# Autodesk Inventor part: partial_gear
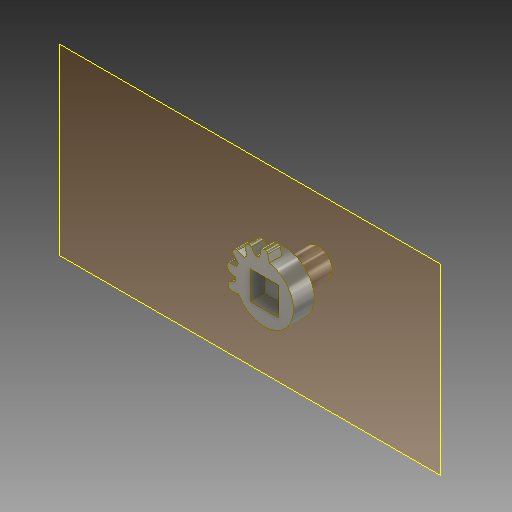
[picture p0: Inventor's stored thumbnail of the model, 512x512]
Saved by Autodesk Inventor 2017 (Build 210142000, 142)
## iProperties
Created: 2017-05
Part Number: partial_gear
Material: Silver
Document SubType Name: Modeling
Designer: 1717440
Density: 10.49 g/cm^3
Appearance: Silver
Author: 1717440
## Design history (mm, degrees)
workplane "Work Plane1"
sketch "Sketch1"
  geometry: L1 (-87.484, -3.82)-(-87.484, 3.711) reference; L2 (-87.484, -3.82)-(-66.896, -5.26) reference; L3 (-42.959, -22.554)-(20.041, -22.554) reference; L4 (20.041, 22.446)-(-42.959, 22.446) reference; L5 (-66.896, 5.151)-(-87.484, 3.711) reference; L6 (-28.459, -15.054)-(-29.709, -12.889) reference; L7 (-29.709, -12.889)-(-33.709, -12.889) reference; L8 (-33.709, -12.889)-(-34.959, -15.054) reference; L9 (-34.959, -15.054)-(-42.959, -15.054) reference; L10 (-42.959, 14.946)-(-40.459, 10.615) reference; L11 (-40.459, 10.615)-(-38.959, 10.615) reference; L12 (-38.959, 10.615)-(-36.459, 14.946) reference; L13 (-36.459, 14.946)-(-34.859, 14.946) reference; L14 (-34.859, 14.946)-(-33.609, 12.78) reference; L15 (-33.609, 12.78)-(-29.609, 12.78) reference; L16 (-29.609, 12.78)-(-28.359, 14.946) reference; L17 (-28.359, 14.946)-(-26.759, 14.946) reference; L18 (-26.759, 14.946)-(-24.259, 10.615) reference; L19 (-24.259, 10.615)-(-22.759, 10.615) reference; L20 (-22.759, 10.615)-(-20.259, 14.946) reference; L21 (-20.259, 14.946)-(-18.659, 14.946) reference; L22 (-18.659, 14.946)-(-16.159, 10.615) reference; L23 (-16.159, 10.615)-(-14.659, 10.615) reference; L24 (-14.659, 10.615)-(-12.159, 14.946) reference; L25 (-12.159, 14.946)-(-10.559, 14.946) reference; L26 (-10.559, 14.946)-(-8.059, 10.615) reference; L27 (-8.059, 10.615)-(-6.559, 10.615) reference; L28 (-6.559, 10.615)-(-4.059, 14.946) reference; L29 (-4.059, 14.946)-(-2.459, 14.946) reference; L30 (-2.459, 14.946)-(0.041, 10.615) reference; L31 (0.041, 10.615)-(1.541, 10.615) reference; L32 (1.541, 10.615)-(4.041, 14.946) reference; L33 (4.041, 14.946)-(5.641, 14.946) reference; L34 (20.041, -15.054)-(19.541, -15.054) reference; L35 (19.541, -15.054)-(17.041, -10.724) reference; L36 (17.041, -10.724)-(15.541, -10.724) reference; L37 (15.541, -10.724)-(13.041, -15.054) reference; L38 (13.041, -15.054)-(11.541, -15.054) reference; L39 (11.541, -15.054)-(10.291, -12.889) reference; L40 (10.291, -12.889)-(6.291, -12.889) reference; L41 (6.291, -12.889)-(5.041, -15.054) reference; L42 (5.041, -15.054)-(3.541, -15.054) reference; L43 (3.541, -15.054)-(1.041, -10.724) reference; L44 (1.041, -10.724)-(-0.459, -10.724) reference; L45 (-0.459, -10.724)-(-2.959, -15.054) reference; L46 (-2.959, -15.054)-(-4.459, -15.054) reference; L47 (-4.459, -15.054)-(-6.959, -10.724) reference; L48 (-6.959, -10.724)-(-8.459, -10.724) reference; L49 (-8.459, -10.724)-(-10.959, -15.054) reference; L50 (-10.959, -15.054)-(-12.459, -15.054) reference; L51 (-12.459, -15.054)-(-14.959, -10.724) reference; L52 (-14.959, -10.724)-(-16.459, -10.724) reference; L53 (-16.459, -10.724)-(-18.959, -15.054) reference; L54 (-18.959, -15.054)-(-20.459, -15.054) reference; L55 (-20.459, -15.054)-(-22.959, -10.724) reference; L56 (-22.959, -10.724)-(-24.459, -10.724) reference; L57 (-24.459, -10.724)-(-26.959, -15.054) reference; L58 (-26.959, -15.054)-(-28.459, -15.054) reference; L59 (12.785, -0.362)-(22.968, -10.545); L60 (12.785, -0.362)-(27.185, -0.362); L61 (22.968, -10.545)-(22.441, -11.071); L62 (22.441, -11.071)-(20.531, -9.969); L63 (22.441, -11.071)-(24.646, -11.071); L64 (19.91, -9.492)-(18.068, -7.65)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; C1 r 10.5 at (12.785, -0.362); A1 r 3 centre (-67.105, -8.252) between (-64.264, -7.288) and (-66.896, -5.26) reference; A2 r 22.5 centre (-42.959, -0.054) between (-64.264, -7.288) and (-42.959, -22.554) reference; A3 r 22.5 centre (20.041, -0.054) between (20.041, -22.554) and (20.041, 22.446) reference; A4 r 22.5 centre (-42.959, -0.054) between (-42.959, 22.446) and (-64.264, 7.179) reference; A5 r 3 centre (-67.105, 8.143) between (-66.896, 5.151) and (-64.264, 7.179) reference; A6 r 15 centre (-42.959, -0.054) between (-42.959, 14.946) and (-42.959, -15.054) reference; A7 r 3 centre (22.031, -7.371) between (19.91, -9.492) and (20.531, -9.969); A8 r 3 centre (19.794, -9.608) between (22.392, -8.108) and (21.915, -7.487); A9 r 3 centre (24.275, -1.976) between (23.456, -4.862) and (24.231, -4.976); A10 r 3 centre (23.411, -5.02) between (24.949, -2.444) and (24.23, -2.134); A11 r 3 centre (23.604, 3.828) between (24.296, 0.909) and (25.028, 1.187); A12 r 3 centre (24.334, 0.749) between (24.421, 3.748) and (23.642, 3.668); A13 r 3 centre (20.191, 8.569) between (22.217, 6.357) and (22.721, 6.957); A14 r 3 centre (22.328, 6.236) between (20.943, 8.897) and (20.301, 8.448); A15 r 3 centre (14.899, 11.046) between (17.747, 10.102) and (17.894, 10.871); A16 r 3 centre (17.902, 10.05) between (15.396, 11.699) and (15.055, 10.994); A17 r 3 centre (9.071, 10.629) between (12.018, 11.193) and (11.771, 11.936); A18 r 3 centre (12.179, 11.224) between (9.187, 11.442) and (9.232, 10.66); A19 r 3 centre (4.185, 7.425) between (6.484, 9.354) and (5.906, 9.883); A20 r 3 centre (6.609, 9.459) between (3.89, 8.191) and (4.311, 7.531); 8 further points
  constraints: 104 end point, 28 point on circle, 15 centre point, 14 point on line, 5 symmetric about line, 2 equal length, 2 horizontal, 2 tangent, 1 parallel, 1 perpendicular, 128 other
  dimensions: "d0" = 21 diameter of C1; "d2" = 14.4 distance of L59.start L59.end; "d3" = 45 deg angle of L59 L60; "d4" = 0.745 distance of L59.end L61.end; "d5" = 2.6 distance of L61.end point (20.189, -9.771); "d6" = 150 deg angle of L63 L62; "d7" = 3 distance of point (20.189, -9.771) L64.end; "d8" = 3 radius of A7; "d11" = 175 deg dimension on L59.start L61.end L104.start
extrude "Extrusion1" new body sketch "Sketch1" distance "d13" = 5; taper "d14" = 0 deg
sketch "Sketch2"
  geometry: C1 r 10.5 at (12.785, -0.362); A1 r 10.5 centre (12.785, -0.362) between (5.012, 6.696) and (19.139, -8.721) reference; A2 r 10.5 centre (12.785, -0.362) between (14.712, 9.959) and (12.223, 10.123) reference; 1 further point
  constraints: 1 centre point, 1 coincident, 1 concentric
extrude "Extrusion2" join sketch "Sketch2" distance "d15" = 2.5; taper "d16" = 0 deg
chamfer "Chamfer1" distance "d17" = 2; stored, may be unused: second distance "d18" = 2, angle "d19" = 45 deg
sketch "Sketch3"
  geometry: L1 (5.1, 5.1)-(-5.1, 5.1); L2 (-5.1, 5.1)-(-5.1, -5.1); L3 (-5.1, -5.1)-(5.1, -5.1); L4 (5.1, -5.1)-(5.1, 5.1); L5 (5.1, 5.1)-(-5.1, -5.1); L6 (-5.1, 5.1)-(5.1, -5.1); C1 r 10.5 at (0, 0) reference; 1 further point
  constraints: 12 end point, 2 midpoint, 2 parallel, 1 horizontal, 1 perpendicular
  dimensions: "d20" = 10.2 distance of L3.end L2.end; "d21" = 10.2 distance of L2.end L1.end
extrude "Extrusion3" cut sketch "Sketch3" distance "d22" = 5; taper "d23" = 0 deg
sketch "Sketch4"
  geometry: C1 r 5 at (-12.785, -0.362); A1 r 10.5 centre (-12.785, -0.362) between (-7.184, 8.519) and (-9.437, 9.59) reference; 1 further point
  constraints: 1 centre point, 1 coincident
  dimensions: "d24" = 10 diameter of C1
extrude "Extrusion4" join sketch "Sketch4" distance "d25" = 12; taper "d26" = 0 deg
sketch "Sketch5"
  geometry: C1 r 10.5 at (0, 0) reference; C2 r 13.111 at (0, 0); C3 r 15.952 at (0, 0); 1 further point
  constraints: 2 centre point, 2 coincident
extrude "Extrusion5" cut sketch "Sketch5" distance "d27" = 24; taper "d28" = 0 deg
sketch "Sketch6"
  geometry: L1 (5.1, 5.1)-(5.1, -5.1) reference; L2 (5.1, -5.1)-(-5.1, -5.1) reference; L3 (0, 0)-(5.1, -3.079); L4 (8.989, -5.427)-(14.213, -8.581); L5 (0, 0)-(3.266, -5.1); L6 (5.663, -8.842)-(8.954, -13.981); A1 r 10.5 centre (0, 0) between (8.989, -5.427) and (5.663, -8.842) reference; A2 r 16.602 centre (0, 0) between (8.954, -13.981) and (14.213, -8.581); 1 further point
  constraints: 8 end point, 4 point on circle, 2 point on line, 1 centre point, 1 coincident
extrude "Extrusion6" cut sketch "Sketch6" distance "d29" = 15.75; taper "d30" = 0 deg
sketch "Sketch7"
  geometry: C1 r 10.5 at (0, 0) reference; C2 r 5 at (0, 0) reference; C3 r 16.847 at (0, 0); 1 further point
  constraints: 1 centre point, 1 coincident
extrude "Extrusion7" cut sketch "Sketch7" distance "d31" = 15.75; taper "d32" = 0 deg
sketch "Sketch8"
  geometry: L1 (0, 0)-(0, 13.629); L2 (0, 13.629)-(1.109, 13.629); L3 (1.109, 13.629)-(1.768, 10.35); L4 (0, 13.629)-(0, 10.5); A1 r 10.5 centre (0, 0) between (1.768, 10.35) and (0, 10.5) reference; 1 further point
  constraints: 8 end point, 2 point on circle, 1 horizontal, 1 point on line, 1 vertical
extrude "Extrusion8" join sketch "Sketch8" distance "d33" = 4.5; taper "d34" = 0 deg
mirror "Mirror1"
fillet "Fillet1" dims "d38" = 1
pattern_circular "Circular Pattern1" dims angle "d36" = 108 deg
body "Solid1"
